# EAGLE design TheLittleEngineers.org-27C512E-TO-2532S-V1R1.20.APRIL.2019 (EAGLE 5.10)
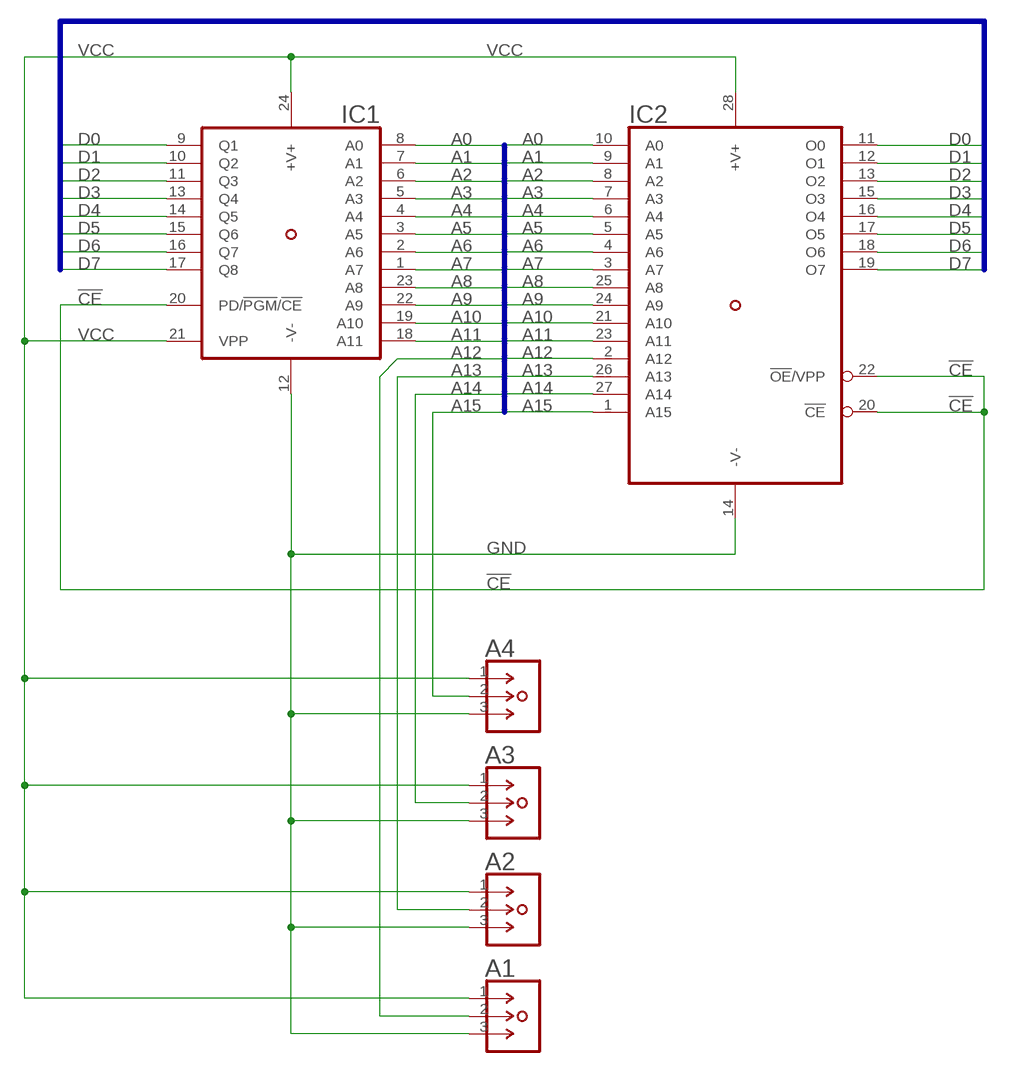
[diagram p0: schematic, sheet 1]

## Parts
A1  1X03-STAGGERED-S  [1X03-STAGGERED]
A2  1X03-STAGGERED-S  [1X03-STAGGERED]
A3  1X03-STAGGERED-S  [1X03-STAGGERED]
A4  1X03-STAGGERED-S  [1X03-STAGGERED]
IC1  TMS2532-NO  [DIL24-6-NO-OUTLINE]
IC2  27C512D-NO  [DIL28-6-NO-OUTLINE]

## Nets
!CE: IC1.20(PD/!PGM!/!CE) IC2.20(!CE) IC2.22(!OE!/VPP)
A0: IC1.8(A0) IC2.10(A0)
A1: IC1.7(A1) IC2.9(A1)
A2: IC1.6(A2) IC2.8(A2)
A3: IC1.5(A3) IC2.7(A3)
A4: IC1.4(A4) IC2.6(A4)
A5: IC1.3(A5) IC2.5(A5)
A6: IC1.2(A6) IC2.4(A6)
A7: IC1.1(A7) IC2.3(A7)
A8: IC1.23(A8) IC2.25(A8)
A9: IC1.22(A9) IC2.24(A9)
A10: IC1.19(A10) IC2.21(A10)
A11: IC1.18(A11) IC2.23(A11)
A12: A1.2 IC2.2(A12)
A13: A2.2 IC2.26(A13)
A14: A3.2 IC2.27(A14)
A15: A4.2 IC2.1(A15)
D0: IC1.9(Q1) IC2.11(O0)
D1: IC1.10(Q2) IC2.12(O1)
D2: IC1.11(Q3) IC2.13(O2)
D3: IC1.13(Q4) IC2.15(O3)
D4: IC1.14(Q5) IC2.16(O4)
D5: IC1.15(Q6) IC2.17(O5)
D6: IC1.16(Q7) IC2.18(O6)
D7: IC1.17(Q8) IC2.19(O7)
GND [power]: A1.3 A2.3 A3.3 A4.3 IC1.12(-V-) IC2.14(-V-)
VCC [power]: A1.1 A2.1 A3.1 A4.1 IC1.21(VPP) IC1.24(+V+) IC2.28(+V+)

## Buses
D[0..7]
A[0..15]

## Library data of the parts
A1-A4 = TheLittleEngineers.org-27C512E-TO-2532S-V1R0.20.APRIL.2019:1X03-STAGGERED: 3-Pin SIP Header Copyright ©07 Jan 2013, by: Robert "The R.A.T." Allen Turner http://www.TheLittleEngineers.org/ TheLittleEngineers@outlook.com OurLittleEngineers@gMail.com You may use these components in your own projects, however, please take note that we CANNOT guarantee the accuracy of these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
IC1 = TheLittleEngineers.org-27C512E-TO-2532S-V1R0.20.APRIL.2019:TMS2532: TMS2532 Copyright ©07 Jan 2013, by: Robert "The R.A.T." Allen Turner http://www.TheLittleEngineers.org/ TheLittleEngineers@outlook.com OurLittleEngineers@gMail.com You may use these components in your own projects, however, please take note that we CANNOT guarantee the accuracy of these components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
IC2 = TheLittleEngineers.org-27C512E-TO-2532S-V1R0.20.APRIL.2019:27C512D: 27C512D Copyright ©07 Jan 2013, by: Robert "The R.A.T." Allen Turner http://www.TheLittleEngineers.org/ TheLittleEngineers@outlook.com OurLittleEngineers@gMail.com You may use these components in your own projects, however, please take note that we CANNOT guarantee the accuracy of these components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

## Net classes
0 default: width 0.203 mm, clearance 0.203 mm
1 power: width 0.381 mm, clearance 0.203 mm

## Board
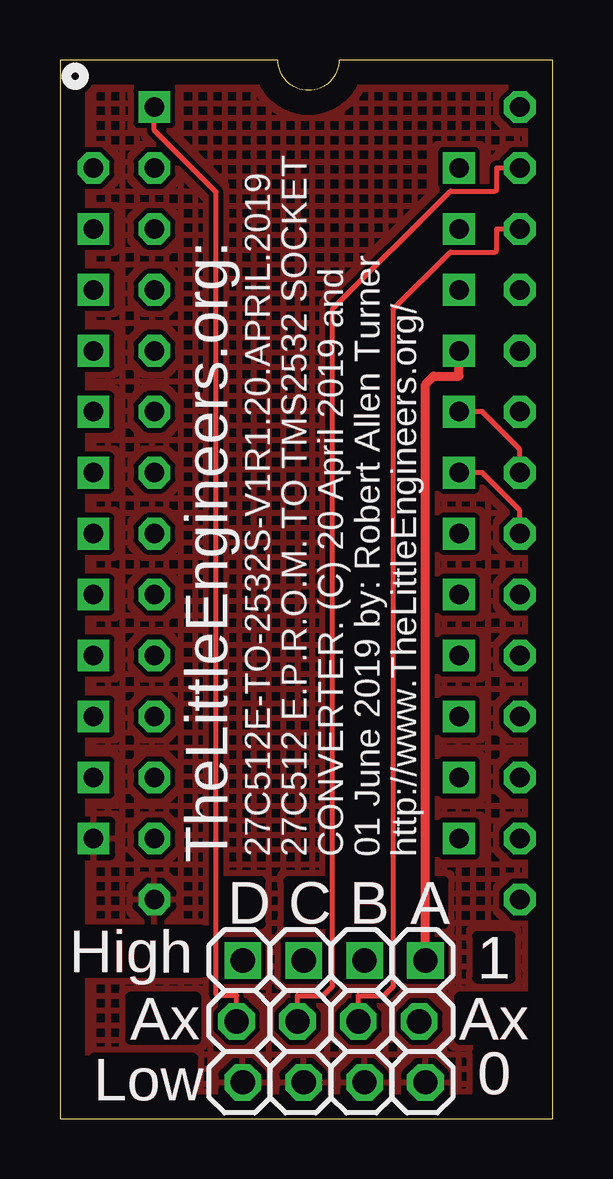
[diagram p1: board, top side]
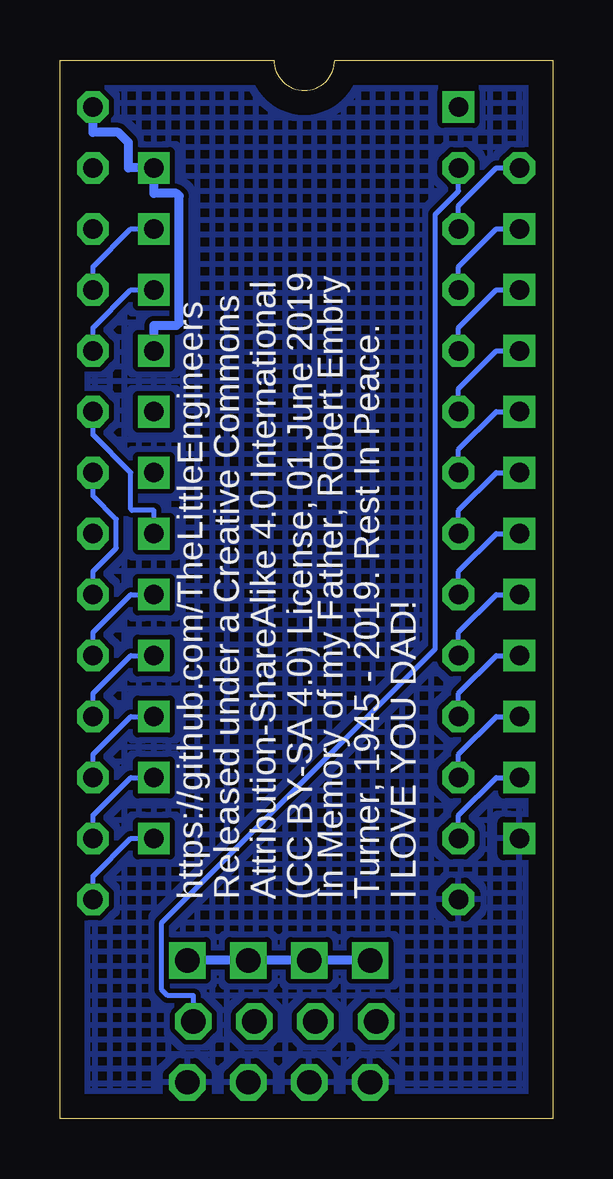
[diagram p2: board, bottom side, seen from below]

Size 20.55 x 44.12 mm. Coordinates in mm from the lower left corner, seen from the top.
Copper layers (1*16): Top 0.035mm / dielectric 1.5mm / Bottom 0.035mm
Design rules "default": minimum track width 10mil, minimum drill 24mil, track to track 8mil, track to pad 8mil, pad to pad 8mil, via to via 8mil, smd to smd 8mil, copper to edge 40mil, drill to drill 8mil, minimum pad ring 10mil, minimum via ring 8mil, stop-mask expansion 4mil, vias tented up to drill 0mil, thermal gap 10mil

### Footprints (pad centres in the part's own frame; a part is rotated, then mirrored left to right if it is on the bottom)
1X03-STAGGERED = drill 1.016 square: 1 -2.54,0.127 | drill 1.016 octagon: 2 0,-0.127; 3 2.54,0.127
DIL24-6-NO-OUTLINE = drill 0.813 octagon: 1 -13.97,-7.62 | drill 0.813 square: 2 -11.43,-7.62; 3 -8.89,-7.62; 4 -6.35,-7.62; 5 -3.81,-7.62; 6 -1.27,-7.62; 7 1.27,-7.62; 8 3.81,-7.62; 9 6.35,-7.62; 10 8.89,-7.62; 11 11.43,-7.62; 12 13.97,-7.62; 13 13.97,7.62; 14 11.43,7.62; 15 8.89,7.62; 16 6.35,7.62; 17 3.81,7.62; 18 1.27,7.62; 19 -1.27,7.62; 20 -3.81,7.62; 21 -6.35,7.62; 22 -8.89,7.62; 23 -11.43,7.62; 24 -13.97,7.62
DIL28-6-NO-OUTLINE = drill 0.813 square: 1 -16.51,-7.62 | drill 0.813 octagon: 2 -13.97,-7.62; 3 -11.43,-7.62; 4 -8.89,-7.62; 5 -6.35,-7.62; 6 -3.81,-7.62; 7 -1.27,-7.62; 8 1.27,-7.62; 9 3.81,-7.62; 10 6.35,-7.62; 11 8.89,-7.62; 12 11.43,-7.62; 13 13.97,-7.62; 14 16.51,-7.62; 15 16.51,7.62; 16 13.97,7.62; 17 11.43,7.62; 18 8.89,7.62; 19 6.35,7.62; 20 3.81,7.62; 21 1.27,7.62; 22 -1.27,7.62; 23 -3.81,7.62; 24 -6.35,7.62; 25 -8.89,7.62; 26 -11.43,7.62; 27 -13.97,7.62; 28 -16.51,7.62

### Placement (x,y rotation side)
A1  15.11,4.06 270 top
A2  12.57,4.06 270 top
A3  10.03,4.06 270 top
A4  7.49,4.06 270 top
IC1  9.02,25.65 270 top
IC2  11.56,25.65 270 top
U$1  [OUTLINE]  1.4,0.25 0 top

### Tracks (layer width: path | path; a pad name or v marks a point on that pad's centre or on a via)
!CE
  Top 0.203: IC1.20 17.6,29.46 19.18,27.89 IC2.22
  Bottom 0.203: IC2.22 19.18,25.96 18.21,24.99 18.21,23.78 19.18,22.81 IC2.20
A0
  Bottom 0.203: IC1.8 2.37,21.84 3.94,20.27 IC2.10
A1
  Bottom 0.203: IC1.7 2.37,24.38 3.94,22.81 IC2.9
A2
  Bottom 0.203: IC1.6 2.37,26.92 3.94,25.35 IC2.8
A3
  Bottom 0.203: IC1.5 2.37,29.46 3.94,27.89 IC2.7
A4
  Bottom 0.203: IC1.4 2.37,32 3.94,30.43 IC2.6
A5
  Bottom 0.203: IC1.3 2.37,34.54 3.94,32.97 IC2.5
A6
  Bottom 0.203: IC1.2 2.37,37.08 3.94,35.51 IC2.4
A7
  Bottom 0.203: IC1.1 2.37,39.62 3.94,38.05 IC2.3
A8
  Bottom 0.203: IC1.23 17.6,37.08 19.18,35.51 IC2.25
A9
  Bottom 0.203: IC1.22 17.6,34.54 19.18,32.97 IC2.24
A10
  Top 0.203: IC1.19 17.6,26.92 19.18,25.35 IC2.21
A11
  Bottom 0.203: IC1.18 16.64,25.35 17.55,25.35 17.6,25.41 17.6,26.92 19.18,28.5 IC2.23
A12
  Bottom 0.203: A1.2 14.99,5.13 16.05,5.13 16.31,5.39 16.31,8.17 4.91,19.58 4.91,37.69 3.94,38.66 IC2.2
A13
  Top 0.203: A2.2 12.45,5.13 13.52,5.13 13.91,5.53 13.91,33.75 16.28,36.12 18.15,36.12 18.21,36.17 18.21,37.08 IC2.26
A14
  Top 0.203: A3.2 9.91,5.13 10.97,5.13 11.37,5.53 11.37,33.75 16.28,38.66 18.15,38.66 18.21,38.71 18.21,39.62 IC2.27
A15
  Top 0.203: A4.2 7.37,5.13 6.58,5.13 6.52,5.19 6.52,38.61 3.94,41.2 IC2.1
D0
  Bottom 0.203: IC1.9 2.37,19.3 3.94,17.73 IC2.11
D1
  Bottom 0.203: IC1.10 2.37,16.76 3.94,15.19 IC2.12
D2
  Bottom 0.203: IC1.11 2.37,14.22 3.94,12.65 IC2.13
D3
  Bottom 0.203: IC1.13 17.6,11.68 19.18,10.11 IC2.15
D4
  Bottom 0.203: IC1.14 17.6,14.22 19.18,12.65 IC2.16
D5
  Bottom 0.203: IC1.15 17.6,16.76 19.18,15.19 IC2.17
D6
  Bottom 0.203: IC1.16 17.6,19.3 19.18,17.73 IC2.18
D7
  Bottom 0.203: IC1.17 17.6,21.84 19.18,20.27 IC2.19
GND
  pour Top (hatched): -0.13,44.2 20.7,44.2 20.7,0 -0.13,0
  pour Bottom (hatched): -0.13,44.2 20.7,44.2 20.7,0 -0.13,0
VCC
  Top 0.381: IC1.21 16.64,30.95 15.58,30.95 15.24,30.61 A1.1
  Bottom 0.381: IC2.28 19.18,41.11 18.12,41.11 17.69,40.68 17.69,39.62 IC1.24 16.64,38.57 15.69,38.57 15.58,38.46 15.58,33.17 15.69,33.06 16.64,33.06 IC1.21 | A1.1 A2.1 A3.1 A4.1
(copper drawn outside any net)
  shapes: Top circle x1

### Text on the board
Top: D | C | B | A | High | 1 | Ax | Ax | Low | 0
tPlace: 27C512E-TO-2532S-V1R1.20.APRIL.2019 | 27C512 E.P.R.O.M. TO TMS2532 SOCKET | CONVERTER. (C) 20 April 2019 and | 01 June 2019 by: Robert Allen Turner | http://www.TheLittleEngineers.org/ | TheLittleEngineers.org: | D | C | B | A | High | 1 | Ax | Ax | Low | 0
bPlace: I LOVE YOU DAD! | Turner, 1945 - 2019. Rest In Peace. | In Memory of my Father, Robert Embry | (CC BY-SA 4.0) License, 01 June 2019 | Attribution-ShareAlike 4.0 International | Released under a Creative Commons | https://github.com/TheLittleEngineers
